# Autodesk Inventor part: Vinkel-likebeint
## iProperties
Author: Jan-Steinar
Shininess: 20.0
PropertySet Name: _Private Model Information
Created: 2001-01
Part Number: Vinkel-likebeint
Document SubType Name: Modeling
Designer: Jan-Steinar
Control State: 0
Master: False
Checked Out: False
PropertySet Name: Design Tracking Control
Density: 0.0
Volumn: 0.0
Area: 0.0
PropertySet Name: Model Information
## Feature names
1. Extrusion1
